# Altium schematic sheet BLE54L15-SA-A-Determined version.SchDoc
size A4
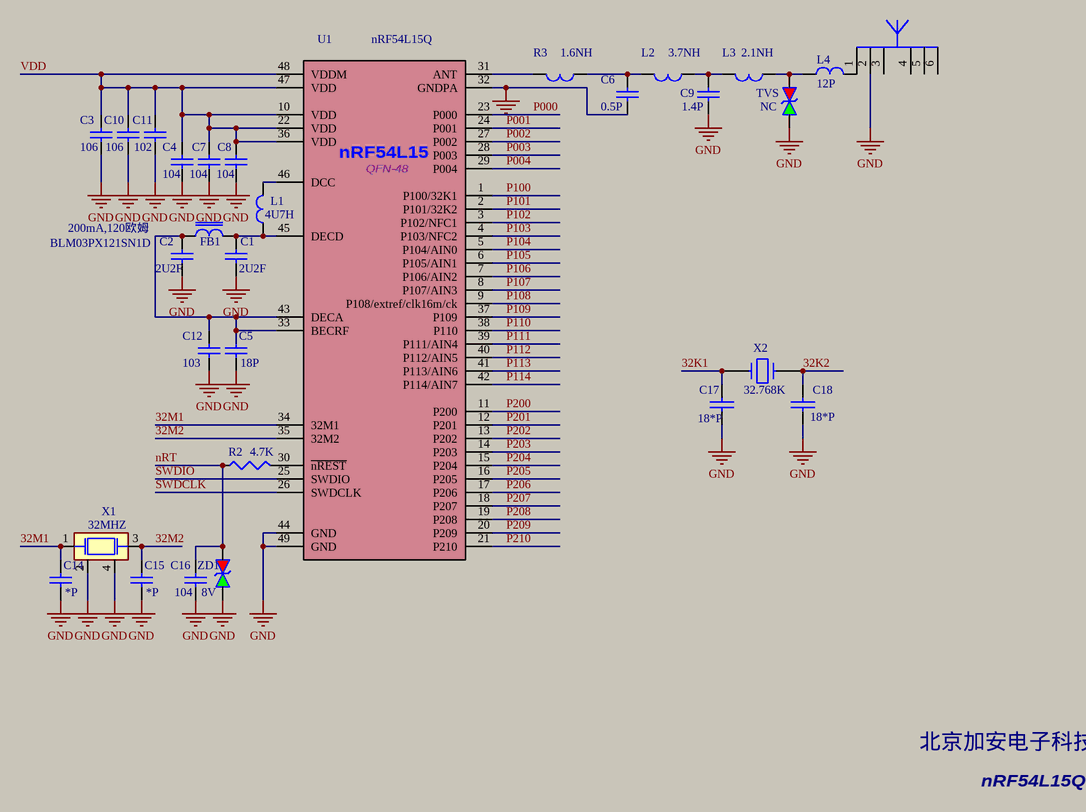
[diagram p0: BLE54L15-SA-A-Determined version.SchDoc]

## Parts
?  (no value)  [1PAD]
C1  2U2F  [0201a]
C2  2U2F  [0201a]
C3  106  [0402a]
C4  104  [0201a]
C5  18P  [0201a]
C6  0.5P  [0201a]
C7  104  [0201a]
C8  104  [0201a]
C9  1.4P  [0201a]
C10  106  [0402a]
C11  102  [0201a]
C12  103  [0201a]
C14  *P  [0201a]
C15  *P  [0201a]
C16  104  [0201a]
C17  18*P  [0201a]
C18  18*P  [0201a]
FB1  BLM03PX121SN1D  [0201a]  (value not drawn)
L1  4U7H  [0603a]
L2  3.7NH  [0201a]
L3  2.1NH  [0201a]
L4  12P  [0201a]
R2  4.7K  [0201a]
R3  1.6NH  [0201a]
TVS  NC  [ESD  TPD1E04U04]
U1  nRF54L15Q  [nRF54L15Q]
X1  32MHZ  [2016]
X2  32.768K  [3215]
ZD1  8V  [TPESD0402G]

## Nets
GND: ?.2(GND) C1.1 C2.1 C3.1 C4.1 C5.1 C6.1 C7.1 C8.1 C9.1 C10.1 C11.1 C12.1 C14.1 C15.1 C16.1 C17.1 C18.1 TVS.2 U1.32(GNDPA) U1.44(GND) U1.49(GND) X1.2 X1.4 ZD1.2
32K1: C17.2 X2.1
32K2: C18.2 X2.2
32M1: C14.2 U1.34(32M1) X1.1
32M2: C15.2 U1.35(32M2) X1.3
nRT: C16.2 R2.1 ZD1.1
P000: U1.23(P000)
P001: U1.24(P001)
P002: U1.27(P002)
P003: U1.28(P003)
P004: U1.29(P004)
P100: U1.1(P100/32K1)
P101: U1.2(P101/32K2)
P102: U1.3(P102/NFC1)
P103: U1.4(P103/NFC2)
P104: U1.5(P104/AIN0)
P105: U1.6(P105/AIN1)
P106: U1.7(P106/AIN2)
P107: U1.8(P107/AIN3)
P108: U1.9(P108/extref/clk16m/ck)
P109: U1.37(P109)
P110: U1.38(P110)
P111: U1.39(P111/AIN4)
P112: U1.40(P112/AIN5)
P113: U1.41(P113/AIN6)
P114: U1.42(P114/AIN7)
P200: U1.11(P200)
P201: U1.12(P201)
P202: U1.13(P202)
P203: U1.14(P203)
P204: U1.15(P204)
P205: U1.16(P205)
P206: U1.17(P206)
P207: U1.18(P207)
P208: U1.19(P208)
P209: U1.20(P209)
P210: U1.21(P210)
SWDCLK: U1.26(SWDCLK)
SWDIO: U1.25(SWDIO)
VDD: C3.2 C4.2 C7.2 C8.2 C10.2 C11.2 U1.10(VDD) U1.22(VDD) U1.36(VDD) U1.47(VDD) U1.48(VDDM)
Net?_1: ?.1(Feed) L4.2
NetC1_2: C1.2 FB1.2 L1.1 U1.45(DECD)
NetC2_2: C2.2 C5.2 C12.2 FB1.1 U1.33(BECRF) U1.43(DECA)
NetC6_2: C6.2 L2.2 R3.1
NetC9_2: C9.2 L2.1 L3.2
NetL1_2: L1.2 U1.46(DCC)
NetL3_1: L3.1 L4.1 TVS.1
NetR2_2: R2.2 U1.30(~{nREST})
NetR3_2: R3.2 U1.31(ANT)

Not connected (* = marked no-connect by the designer): ? 3(GND) 4(Feed) 5 6

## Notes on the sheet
- BLM03PX121SN1D
- 200mA,120欧姆
- 北京加安电子科技有限公司
- nRF54L15Q

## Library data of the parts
? = 2G4 5G C
C1-C12 = Cap: Capacitor
C14-C16 = Cap: Capacitor; Value: 10uF/50V/1206
C17 C18 = CAP: Capacitor
FB1 = IN: 贴片电感
L1-L4 R3 = INDUCTOR: 电感
R2 = RES1
TVS ZD1 = ESD
X1 = XTAL_4_PINS: 4P晶振
X2 = CRYSTAL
